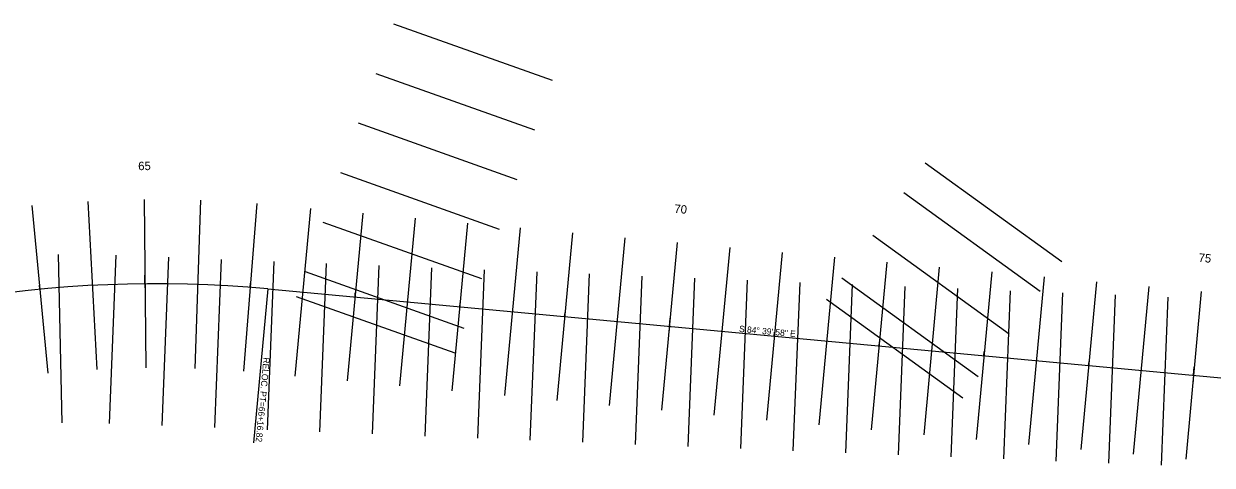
# Model space of a CAD drawing. Extents: x 1965757 to 1970272, y 1117058 to 1118406.
# Drawn here: x 1968046 to 1969174, y 1117811 to 1118230 of the extents above; entities that cross this region are included whole.
import ezdxf

# ---------------------------------------------------------------- set-up
doc = ezdxf.new("R2010")
doc.units = 0
for name, color, linetype in [('RD_HC_CL_Rel', 7, 'Continuous'), ('RD_HC_Data_Rel', 7, 'Continuous'), ('RD_HC_Data_Tic_Rel', 7, 'Continuous'), ('RD_HC_TX_Rel_Sta50', 7, 'Continuous'), ('RD_PD_PatLn1', 7, 'Continuous'), ('RD_PD_PatLn2', 7, 'Continuous'), ('RD_PD_PatLn3', 7, 'Continuous')]:
    doc.layers.add(name, color=color, linetype=linetype)

msp = doc.modelspace()

# ---------------------------------------------------------------- linework, layer by layer
at = {"layer": 'RD_HC_CL_Rel'}
msp.add_line((1968277.4, 1117978.5), (1969226.4, 1117889.9), dxfattribs=at)
msp.add_arc((1968170.8, 1116837.5), 1145.9, 84.6661, 115.0463, dxfattribs=at)
at = {"layer": 'RD_HC_Data_Rel'}
msp.add_line((1968277.4, 1117978.5), (1968263.7, 1117832.3), dxfattribs=at)
at = {"layer": 'RD_HC_Data_Tic_Rel'}
for p, q in [((1968160.7, 1117983.4), (1968160.6, 1117991.4)), ((1968060.9, 1117978.1), (1968060.5, 1117982.1)), ((1968160.7, 1117983.4), (1968160.8, 1117975.4)), ((1968260.6, 1117979.9), (1968260.9, 1117983.9)), ((1968360.2, 1117970.7), (1968360.5, 1117974.7)), ((1968459.7, 1117961.4), (1968460.1, 1117965.4)), ((1968559.3, 1117952.1), (1968559.7, 1117956.1)), ((1968658.9, 1117942.8), (1968659.6, 1117950.8)), ((1968658.9, 1117942.8), (1968658.1, 1117934.9)), ((1968758.4, 1117933.5), (1968758.8, 1117937.5)), ((1968858, 1117924.3), (1968858.4, 1117928.2)), ((1968957.6, 1117915), (1968957.9, 1117918.9)), ((1969057.1, 1117905.7), (1969057.5, 1117909.6)), ((1969156.7, 1117896.4), (1969157.4, 1117904.3)), ((1969156.7, 1117896.4), (1969156, 1117888.4))]:
    msp.add_line(p, q, dxfattribs=at)
at = {"layer": 'RD_PD_PatLn1'}
for p, q in [((1968078.2, 1118011.3), (1968081.7, 1117851.3)), ((1968133.1, 1118010.5), (1968126.7, 1117850.6)), ((1968183.1, 1118008.5), (1968176.7, 1117848.6)), ((1968233, 1118006.5), (1968226.7, 1117846.7)), ((1968283, 1118004.6), (1968276.6, 1117844.7)), ((1968332.9, 1118002.6), (1968326.6, 1117842.7)), ((1968382.9, 1118000.6), (1968376.6, 1117840.7)), ((1968432.9, 1117998.6), (1968426.5, 1117838.7)), ((1968482.8, 1117996.6), (1968476.5, 1117836.7)), ((1968532.8, 1117994.6), (1968526.4, 1117834.8)), ((1968582.7, 1117992.7), (1968576.4, 1117832.8)), ((1968632.7, 1117990.7), (1968626.4, 1117830.8)), ((1968682.7, 1117988.7), (1968676.3, 1117828.8)), ((1968732.6, 1117986.7), (1968726.3, 1117826.8)), ((1968782.6, 1117984.7), (1968776.2, 1117824.8)), ((1968832.5, 1117982.7), (1968826.2, 1117822.9)), ((1968882.5, 1117980.8), (1968876.2, 1117820.9)), ((1968932.5, 1117978.8), (1968926.1, 1117818.9)), ((1968982.4, 1117976.8), (1968976.1, 1117816.9)), ((1969032.4, 1117974.8), (1969026, 1117814.9)), ((1969082.3, 1117972.8), (1969076, 1117812.9)), ((1969132.3, 1117970.8), (1969126, 1117811))]:
    msp.add_line(p, q, dxfattribs=at)
at = {"layer": 'RD_PD_PatLn2'}
for p, q in [((1968053.2, 1118057.8), (1968068.5, 1117898.5)), ((1968106.5, 1118061.7), (1968114.9, 1117902)), ((1968160, 1118063.4), (1968161.4, 1117903.4)), ((1968213.5, 1118062.7), (1968207.9, 1117902.8)), ((1968266.9, 1118059.7), (1968254.3, 1117900.2)), ((1968317.8, 1118055), (1968302.9, 1117895.7)), ((1968367.6, 1118050.4), (1968352.7, 1117891.1)), ((1968417.4, 1118045.7), (1968402.5, 1117886.4)), ((1968467.2, 1118041.1), (1968452.3, 1117881.8)), ((1968517, 1118036.4), (1968502.1, 1117877.1)), ((1968566.7, 1118031.8), (1968551.9, 1117872.5)), ((1968616.5, 1118027.1), (1968601.6, 1117867.8)), ((1968666.3, 1118022.5), (1968651.4, 1117863.2)), ((1968716.1, 1118017.9), (1968701.2, 1117858.5)), ((1968765.9, 1118013.2), (1968751, 1117853.9)), ((1968815.7, 1118008.6), (1968800.8, 1117849.2)), ((1968865.4, 1118003.9), (1968850.6, 1117844.6)), ((1968915.2, 1117999.3), (1968900.4, 1117840)), ((1968965, 1117994.6), (1968950.1, 1117835.3)), ((1969014.8, 1117990), (1968999.9, 1117830.7)), ((1969064.6, 1117985.3), (1969049.7, 1117826)), ((1969114.4, 1117980.7), (1969099.5, 1117821.4)), ((1969164.1, 1117976), (1969149.3, 1117816.7))]:
    msp.add_line(p, q, dxfattribs=at)
at = {"layer": 'RD_PD_PatLn3'}
for p, q in [((1968396.8, 1118230.4), (1968547.5, 1118176.7)), ((1968380, 1118183.3), (1968530.7, 1118129.6)), ((1968363.2, 1118136.2), (1968513.9, 1118082.5)), ((1968901.9, 1118098.4), (1969031.5, 1118004.5)), ((1968346.4, 1118089.1), (1968497.1, 1118035.4)), ((1968881.4, 1118070.1), (1969011, 1117976.2)), ((1968329.6, 1118042), (1968480.3, 1117988.3)), ((1968852.1, 1118029.6), (1968981.6, 1117935.7)), ((1968312.8, 1117994.9), (1968463.5, 1117941.2)), ((1968822.7, 1117989.1), (1968952.3, 1117895.2)), ((1968304.4, 1117971.4), (1968455.1, 1117917.7)), ((1968808.1, 1117968.8), (1968937.6, 1117875))]:
    msp.add_line(p, q, dxfattribs=at)

# ---------------------------------------------------------------- texts
at = {"layer": 'RD_HC_Data_Rel'}
for s, rotation, p in [('S 84%%d 39\' 58" E', 354.6661, (1968724.8, 1117937.7)), ('RELOC. PT=66+16.82', 264.6661, (1968273.3, 1117913.6))]:
    msp.add_text(s, height=6, rotation=rotation, dxfattribs=at).set_placement(p)
at = {"layer": 'RD_HC_TX_Rel_Sta50'}
for s, rotation, p in [('65', 0.5072, (1968154.3, 1118091.3)), ('70', 354.6661, (1968663.3, 1118050.9)), ('75', 354.6661, (1969161.3, 1118004.4))]:
    msp.add_text(s, height=8, rotation=rotation, dxfattribs=at).set_placement(p)

doc.saveas('drawing.dxf')
